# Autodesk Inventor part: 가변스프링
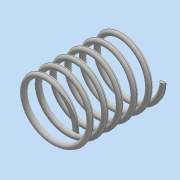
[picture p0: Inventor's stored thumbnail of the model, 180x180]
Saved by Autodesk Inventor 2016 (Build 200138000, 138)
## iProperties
Created: 2018-11
Part Number: 가변스프링
Material: 일반
Document SubType Name: Modeling
Designer: user
Density: 1 g/cm^3
Appearance: 기본값
Mass: 10.5248 g
Surface Area: 106.475 cm^2
Volume: 10.5248 cm^3
Author: user
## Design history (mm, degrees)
sketch "스케치1"
  geometry: L1 (0, 0)-(22.5, 0); L2 (22.5, 0)-(22.5, 67.25); L3 (22.5, 67.25)-(0, 67.25); L4 (0, 67.25)-(0, 0); C1 r 2 at (22.5, 0)
  constraints: 8 end point, 2 parallel, 1 centre point, 1 coincident, 1 horizontal, 1 perpendicular
  dimensions: "d0" = 4 diameter of C1; "d1" = 45 diameter of L2 L4; "d2" = 67.25 distance of L3.end L1.start (derived)
feature "코일1" sketch "스케치1" pitch "d3" = 10; turns "d5" = 6; dims "d4" = 67.25 (= d2), "d6" = 0, angle "d7" = 90 deg, angle "d8" = 90 deg, "d9" = 0, "d10" = 0
sketch "스케치2"
  geometry: L1 (-49.505, 0)-(49.505, 0); L2 (49.505, 0)-(49.505, 67.25); L3 (49.505, 67.25)-(-49.505, 67.25); L4 (-49.505, 67.25)-(-49.505, 0); 2 further points
  constraints: 8 end point, 2 parallel, 1 coincident, 1 horizontal, 1 midpoint, 1 perpendicular
  dimensions: "d11" = 99.00983 distance between parallel lines of L2 L4; "d12" = 67.25 distance between parallel lines of L1 L3 (= d2)
extrude "돌출1" sketch "스케치2" stored distance "d13" = 100; taper "d14" = 0 deg
node "솔리드1"
